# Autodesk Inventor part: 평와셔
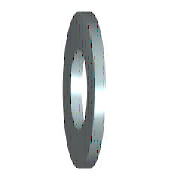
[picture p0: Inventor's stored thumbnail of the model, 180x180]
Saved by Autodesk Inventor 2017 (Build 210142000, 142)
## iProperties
IsCustomPart: 1
Created: 2012-02
Part Number: 평와셔
Material: 강철, 연강
Description: 평면 와셔 - 초대형 시리즈 - 제품 등급 C
Document SubType Name: Modeling
Standard: ISO 7094
Designer: mduedu
Standard Revision: Second edition 2000-06-01
Standards Organization: ISO
Language: ko-KR
Size Designation: ST 5 - 100 HV
Categories: <MemberInstance><Categories><Category DisplayName="조임쇠" InternalName="e4da775c-781d-43d5-af7c-5136215cf5a6" Mnemonic="FSTN"><Category DisplayName="와셔" InternalN
Density: 7.86 g/cm^3
Mass: 3.62677 g
Surface Area: 6.09076 cm^2
Volume: 0.461421 cm^3
Appearance: 강철
Author: mduedu
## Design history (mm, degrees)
sketch "스케치"
  geometry: C1 r 9 at (0, 0); C2 r 2.75 at (0, 0); 1 further point
  constraints: 2 centre point, 2 coincident
  dimensions: "d0" = 5.5 diameter of C2 (= SD1); "d1" = 18 diameter of C1 (= SD2)
extrude "본체" new body sketch "스케치" distance "d2" = 2 (= SD); taper "d3" = 0 deg
workaxis "Work Axis1"
workplane "Work Plane1"
body "Solid1"
other parameters: "SD1" = 5.5 [user parameter; used in 1 equation term], "SD2" = 18 [user parameter; used in 1 equation term], "SD" = 2 [user parameter; used in 1 equation term], "d4" = 0, "d5" = 0, "d6" = 0, "d7" = 0, "NND" = 5 [user parameter]
